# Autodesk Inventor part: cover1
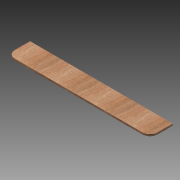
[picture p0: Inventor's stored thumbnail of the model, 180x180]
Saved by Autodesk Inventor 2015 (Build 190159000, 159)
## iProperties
Created: 2015-04
Part Number: cover1
Material: Wood (Birch)
Document SubType Name: Modeling
Designer: sungeun
Density: 0.55 g/cm^3
Appearance: Birch - Natural Polished
Author: sungeun
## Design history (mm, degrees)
sketch "Sketch1"
  geometry: L1 (-470, 82)-(-470, 182); L2 (-470, 182)-(0, 182); L3 (0, 182)-(0, 72); L4 (470, 182)-(0, 182); L5 (470, 82)-(470, 182); L6 (-420, 32)-(420, 32); A1 r 50 centre (-420, 82) between (-470, 82) and (-420, 32); A2 r 50 centre (420, 82) between (420, 32) and (470, 82); 2 further points
  constraints: 12 end point, 4 point on circle, 4 tangent, 2 centre point, 2 horizontal, 2 point on line, 1 midpoint, 1 symmetric about line, 1 vertical
  dimensions: "d2" = 90 deg angle of L2 L1; "d8" = 470 distance of L1.end L2.end; "d21" = 50 radius of A1; "d22" = 50 radius of A2; "d23" = 150 distance between parallel lines of L2 L6
extrude "Extrusion1" new body sketch "Sketch1" distance "d6" = 12 (= thickness); taper "d7" = 0 deg
body "Solid1"
other parameters: "thickness" = 12 [user parameter; used in 1 equation term]
